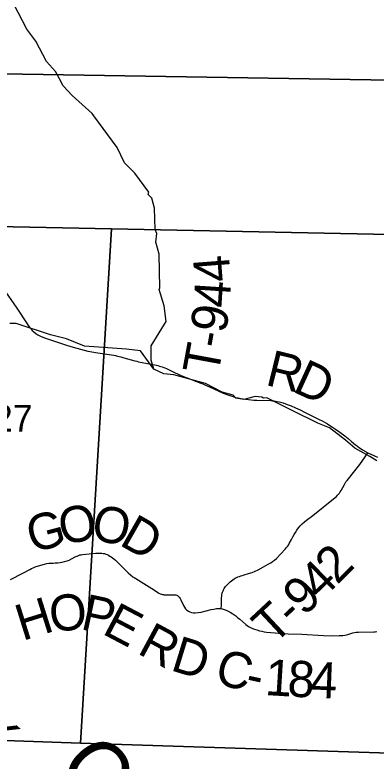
# Model space of a CAD drawing. Extents: x 0 to 34, y 0 to 22.
# Drawn here: x 24.457 to 25.024, y 16.486 to 17.66 of the extents above; entities that cross this region are included whole.
import ezdxf

# ---------------------------------------------------------------- set-up
doc = ezdxf.new("R2010")
doc.units = 0
for name, color, linetype in [('GM_X_County_Road', 7, 'Continuous'), ('GM_X_County_Road_Text', 7, 'Continuous'), ('GM_X_Minor_River', 7, 'Continuous'), ('GM_X_Minor_River_Text', 7, 'Continuous'), ('GM_X_Section', 7, 'Continuous'), ('GM_X_Section_Text', 7, 'Continuous'), ('GM_X_Township_Road', 7, 'Continuous'), ('GM_X_Township_Road_Text', 7, 'Continuous')]:
    doc.layers.add(name, color=color, linetype=linetype)

msp = doc.modelspace()

# ---------------------------------------------------------------- linework, layer by layer
at = {"layer": 'GM_X_County_Road'}
for points in [[(24.4374, 17.2311), (24.4597, 17.1981), (24.4758, 17.1738), (24.4776, 17.1712), (24.4797, 17.1685), (24.4816, 17.1661), (24.484, 17.1633), (24.4865, 17.1609), (24.4893, 17.1585), (24.4928, 17.1562), (24.4968, 17.1541), (24.5004, 17.1526), (24.5045, 17.1509), (24.538, 17.1399), (24.5429, 17.1384), (24.548, 17.137), (24.5713, 17.1309), (24.5747, 17.1302), (24.5778, 17.1296), (24.5805, 17.1291), (24.5832, 17.1286), (24.612, 17.1242), (24.615, 17.1236), (24.6179, 17.123), (24.6203, 17.1224), (24.6231, 17.1217), (24.6278, 17.1203)], [(24.6278, 17.1203), (24.6449, 17.1154), (24.6481, 17.1147), (24.6508, 17.114), (24.679, 17.1086), (24.6815, 17.108), (24.6838, 17.1073), (24.6862, 17.1065), (24.6883, 17.1058), (24.6905, 17.105), (24.6925, 17.1042), (24.6949, 17.1032), (24.7074, 17.0973), (24.7192, 17.0917), (24.749, 17.0802), (24.7519, 17.0791), (24.7553, 17.0777), (24.7587, 17.0763), (24.7624, 17.0746), (24.7773, 17.0677), (24.7838, 17.0648), (24.7897, 17.0625), (24.7944, 17.0607), (24.7994, 17.0591), (24.8035, 17.058), (24.8076, 17.0571), (24.8115, 17.0563), (24.8155, 17.0557), (24.8198, 17.0551), (24.8238, 17.0546), (24.8279, 17.0541), (24.8319, 17.0538), (24.8368, 17.0535), (24.8589, 17.0528), (24.8616, 17.0526), (24.864, 17.0524), (24.8664, 17.052), (24.8718, 17.0508), (24.878, 17.0492), (24.8845, 17.0469), (24.8907, 17.0445), (24.8978, 17.0414), (24.9047, 17.0381), (24.912, 17.0345), (24.9348, 17.0232), (24.9393, 17.021), (24.9433, 17.0187), (24.9477, 17.0162), (24.9515, 17.0139), (24.9555, 17.0113), (24.9604, 17.008), (24.9674, 17.0034), (24.9751, 16.9974), (24.9802, 16.9931), (24.9858, 16.9885), (24.9919, 16.9833), (24.9928, 16.9826)], [(24.9928, 16.9826), (24.9955, 16.9806), (24.9984, 16.9785), (25.0009, 16.9768), (25.0028, 16.9756), (25.0114, 16.9709), (25.0219, 16.9658), (25.0267, 16.9639)], [(24.4495, 16.7713), (24.469, 16.7811), (24.4801, 16.7872), (24.4825, 16.7885), (24.4852, 16.7898), (24.4887, 16.7912), (24.4939, 16.7928), (24.5033, 16.7956), (24.5066, 16.7964), (24.51, 16.7968), (24.5135, 16.7971), (24.5167, 16.7972), (24.5202, 16.7973), (24.5241, 16.7976), (24.5277, 16.7981), (24.5312, 16.7986), (24.5346, 16.7995), (24.5386, 16.8007), (24.542, 16.802), (24.5457, 16.8037), (24.5526, 16.8073), (24.5546, 16.8083), (24.5566, 16.8092), (24.5587, 16.8099), (24.5606, 16.8104), (24.5627, 16.8107), (24.5836, 16.8126), (24.5861, 16.8128), (24.5885, 16.8129), (24.5908, 16.8129), (24.5931, 16.8128), (24.5953, 16.8125), (24.5976, 16.812), (24.5997, 16.8114), (24.6015, 16.8107), (24.6037, 16.8097), (24.6059, 16.8083), (24.608, 16.807), (24.6102, 16.8054), (24.6123, 16.8037), (24.6146, 16.8019), (24.617, 16.7996), (24.6195, 16.7972), (24.6347, 16.7817), (24.6421, 16.7756), (24.644, 16.7743), (24.6465, 16.7727), (24.6716, 16.7574), (24.681, 16.7512), (24.6831, 16.75), (24.6851, 16.749), (24.687, 16.7483), (24.6887, 16.7478), (24.6902, 16.7475), (24.6912, 16.7474), (24.6921, 16.7473), (24.6982, 16.7474), (24.7041, 16.7474), (24.7061, 16.7474), (24.7078, 16.7473), (24.7094, 16.7471), (24.711, 16.7466), (24.7122, 16.746), (24.7133, 16.7451), (24.7143, 16.7442), (24.7153, 16.7429), (24.7162, 16.7414), (24.7172, 16.7395), (24.7215, 16.7305), (24.7232, 16.7277), (24.7249, 16.7253), (24.727, 16.7231), (24.7295, 16.7213), (24.7317, 16.7202), (24.734, 16.7195), (24.7371, 16.719), (24.7402, 16.7189), (24.7445, 16.7193), (24.7493, 16.7201), (24.7649, 16.7239), (24.7693, 16.7249), (24.7734, 16.7256), (24.7762, 16.7259), (24.7785, 16.7259), (24.7809, 16.7257), (24.7826, 16.7252), (24.7842, 16.7247), (24.7869, 16.7237), (24.7907, 16.7218), (24.7947, 16.7197), (24.7992, 16.7171), (24.8036, 16.714), (24.8067, 16.7115), (24.8101, 16.7087), (24.8195, 16.7007), (24.8214, 16.6989), (24.8239, 16.6972), (24.8268, 16.6956), (24.8299, 16.6943), (24.8333, 16.693), (24.837, 16.6919), (24.8412, 16.6906), (24.8446, 16.6898), (24.8482, 16.6892), (24.8518, 16.6887), (24.8655, 16.6873), (24.8755, 16.6864), (24.8802, 16.6861), (24.8861, 16.6858), (24.9073, 16.6851), (24.9416, 16.683), (24.9544, 16.6828), (24.9664, 16.683), (24.9695, 16.6832), (24.9722, 16.6833), (24.9752, 16.6838), (24.9783, 16.6845), (24.9844, 16.6862), (24.9877, 16.6873), (24.9905, 16.6879), (24.9932, 16.6884), (24.9966, 16.6886), (25.0206, 16.6888), (25.023, 16.689), (25.0254, 16.6893)]]:
    msp.add_lwpolyline(points, dxfattribs=at)
at = {"layer": 'GM_X_Minor_River'}
for points in [[(24.6672, 17.3811), (24.6449, 17.4107), (24.629, 17.427), (24.6173, 17.4513), (24.5809, 17.501), (24.5779, 17.5048), (24.5469, 17.5329), (24.5325, 17.5484), (24.5268, 17.5591), (24.5204, 17.5708), (24.5064, 17.5864), (24.4897, 17.6183), (24.4753, 17.6376), (24.4549, 17.6767), (24.4492, 17.6812), (24.436, 17.704), (24.4098, 17.7579), (24.3909, 17.7894), (24.3754, 17.8297), (24.3757, 17.8483), (24.375, 17.8544), (24.3795, 17.8837), (24.3806, 17.884)], [(25.0256, 16.9579), (25.0146, 16.9647), (24.9908, 16.9779), (24.976, 16.9908), (24.9511, 17.0101), (24.9325, 17.0173), (24.8936, 17.0366), (24.8524, 17.057), (24.8475, 17.0566), (24.8448, 17.0581), (24.8342, 17.0593), (24.8165, 17.0547), (24.804, 17.0569), (24.7994, 17.0615), (24.7824, 17.066), (24.756, 17.08), (24.7064, 17.0932), (24.6905, 17.095), (24.675, 17.1022), (24.6709, 17.1166), (24.6708, 17.1391), (24.6916, 17.1733), (24.6946, 17.1775), (24.6912, 17.2018), (24.6832, 17.2276), (24.6844, 17.2303), (24.6836, 17.2831), (24.6779, 17.3021), (24.6798, 17.3158), (24.6771, 17.3219), (24.6759, 17.3557), (24.6721, 17.3713), (24.6661, 17.3773), (24.6672, 17.3811)], [(24.675, 17.1023), (24.6542, 17.131), (24.6319, 17.1336), (24.5658, 17.1384), (24.5378, 17.1502), (24.5128, 17.1566), (24.4584, 17.1743), (24.4485, 17.1743)]]:
    msp.add_lwpolyline(points, dxfattribs=at)
at = {"layer": 'GM_X_Section'}
for points in [[(24.0951, 17.7788), (25.1245, 17.7506), (25.1122, 17.5559), (24.0818, 17.5731)], [(24.0815, 17.5702), (24.0818, 17.5731), (25.1122, 17.5559), (25.097, 17.3132), (24.6087, 17.3232), (24.0677, 17.3343)], [(24.6087, 17.3232), (24.5596, 16.5135), (24.0115, 16.5331), (24.0677, 17.3343)], [(25.097, 17.3132), (25.0459, 16.4982), (24.5596, 16.5135), (24.6087, 17.3232)], [(24.5596, 16.5135), (25.0459, 16.4982), (25.0486, 16.498), (25.0369, 16.3074), (25.0112, 15.8778), (24.9883, 15.4512), (23.9474, 15.5054), (24.0115, 16.5331)]]:
    msp.add_lwpolyline(points, close=True, dxfattribs=at)
at = {"layer": 'GM_X_Township_Road'}
msp.add_lwpolyline([(24.7809, 16.7257), (24.7811, 16.7307), (24.7814, 16.7396), (24.7815, 16.7425), (24.7817, 16.745), (24.7821, 16.7474), (24.7825, 16.7496), (24.7831, 16.7515), (24.7837, 16.7534), (24.7845, 16.7551), (24.7856, 16.757), (24.7867, 16.7588), (24.7878, 16.7603), (24.789, 16.7617), (24.7908, 16.7635), (24.7929, 16.7656), (24.7949, 16.7675), (24.797, 16.7693), (24.799, 16.7708), (24.8012, 16.7723), (24.803, 16.7733), (24.8049, 16.7743), (24.8071, 16.7754), (24.8094, 16.7762), (24.8115, 16.7769), (24.8141, 16.7777), (24.8167, 16.7785), (24.8238, 16.7807), (24.8296, 16.7826), (24.8342, 16.7844), (24.8388, 16.7867), (24.8473, 16.7912), (24.8549, 16.7952), (24.8588, 16.7975), (24.8617, 16.7995), (24.8644, 16.8016), (24.8677, 16.8046), (24.8814, 16.8189), (24.8832, 16.821), (24.8851, 16.8235), (24.8865, 16.8255), (24.8879, 16.8279), (24.8913, 16.8344), (24.8935, 16.8385), (24.8956, 16.8422), (24.8976, 16.8455), (24.8999, 16.849), (24.9023, 16.8524), (24.9052, 16.8558), (24.9083, 16.8591), (24.9117, 16.8622), (24.9149, 16.8647), (24.9246, 16.8723), (24.96, 16.9005), (24.9619, 16.9021), (24.9636, 16.9038), (24.9651, 16.9056), (24.9665, 16.9072), (24.968, 16.9094), (24.9692, 16.9114), (24.9746, 16.9211), (24.9758, 16.923), (24.9769, 16.9249), (24.9786, 16.9271), (24.9985, 16.9525), (25.007, 16.9643), (25.0114, 16.9709)], dxfattribs=at)

# ---------------------------------------------------------------- texts
at = {"layer": 'GM_X_County_Road_Text'}
for s, rotation, p in [('R', 346.3358, (24.8486, 17.0779)), ('D', 335.3756, (24.8912, 17.0678)), ('O', 10.6302, (24.5309, 16.8255)), ('O', 348.754, (24.5744, 16.8348)), ('G', 14.9251, (24.4837, 16.8129)), ('D', 330.2452, (24.6189, 16.8267)), ('O', 5.0846, (24.513, 16.6887)), ('P', 347.959, (24.5584, 16.6934)), ('H', 17.3671, (24.4685, 16.6744)), ('E', 332.2063, (24.592, 16.6868)), ('R', 331.6612, (24.6472, 16.6559)), ('D', 342.9484, (24.6995, 16.629)), ('C', 344.7009, (24.7683, 16.6089)), ('1', 356.5063, (24.8487, 16.5896)), ('8', 356.9001, (24.8841, 16.5875)), ('4', 357.717, (24.9199, 16.5855)), ('-', 347.826, (24.8166, 16.5958)), ('K', 318.0358, (24.3931, 16.5252))]:
    msp.add_text(s, height=0.0568, rotation=rotation, dxfattribs=at).set_placement(p)
at = {"layer": 'GM_X_Minor_River_Text'}
msp.add_text('Creek', height=0.09469, rotation=310.1368, dxfattribs=at).set_placement((24.5206, 16.4758))
at = {"layer": 'GM_X_Section_Text'}
msp.add_text('27', height=0.04186, rotation=0, dxfattribs=at).set_placement((24.4222, 17.0042))
at = {"layer": 'GM_X_Township_Road_Text'}
for s, rotation, p in [('4', 94.394, (24.7961, 17.2414)), ('4', 86.3482, (24.7939, 17.1978)), ('9', 81.0918, (24.7879, 17.1575)), ('-', 79.8371, (24.7835, 17.1332)), ('T', 79.5276, (24.7758, 17.0911)), ('2', 45.3268, (24.9632, 16.7621)), ('4', 43.961, (24.937, 16.7367)), ('9', 43.407, (24.9111, 16.7123)), ('T', 43.0875, (24.8628, 16.6671)), ('-', 43.1508, (24.8939, 16.6961))]:
    msp.add_text(s, height=0.0568, rotation=rotation, dxfattribs=at).set_placement(p)

doc.saveas('drawing.dxf')
